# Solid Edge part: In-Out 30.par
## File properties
Title: In - Out 30
Author: DESYS
Template: Normal.par
Last saved by: s.pallini
Revision: 8
Application: Solid Edge
Tipo di contenuto documento: 0
Precisione: 0,990
Document Number: 8020
Revision: 0
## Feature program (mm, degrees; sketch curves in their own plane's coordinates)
sketch for "unnamed RevolvedProtrusion 1" plane through (0, 0, 0) normal (0, -1, 0) x-axis (1, 0, 0)
  line (-147.5, 40.4136) -> (-147.5, 38.4136)
  arc centre (-145.5, 38.4136) radius 2 from (-147.5, 38.4136) to (-145.5, 36.4136) ccw
  line (-145.5, 36.4136) -> (-141.6472, 36.4136)
  arc centre (-141.6472, 31.4136) radius 5 from (-136.6496, 31.2592) to (-141.6472, 36.4136) ccw
  arc centre (-16.7068, 27.5544) radius 120 from (-136.6496, 31.2592) to (-72.9674, -78.4396) ccw
  arc centre (-80, -91.6889) radius 15 from (-65, -91.6889) to (-72.9674, -78.4396) ccw
  line (-65, -108.5864) -> (-65, -91.6889)
  arc centre (-59, -108.5864) radius 6 from (-65, -108.5864) to (-59, -114.5864) ccw
  line (-25, -114.5864) -> (-59, -114.5864)
  line (-25, -74.5864) -> (-25, -114.5864)
  arc centre (-17.1637, 35.1341) radius 110 from (-127.0888, 39.1923) to (-25, -74.5864) ccw
  arc centre (-133.0847, 39.4136) radius 6 from (-127.0888, 39.1923) to (-133.0847, 45.4136) ccw
  line (-142.5, 45.4136) -> (-133.0847, 45.4136)
  arc centre (-142.5, 40.4136) radius 5 from (-147.5, 40.4136) to (-142.5, 45.4136) cw
  dimension (linear) = 25
revolve "unnamed RevolvedProtrusion 1" add full turn 360 deg
fillet "unnamed Round 1"
fillet "Rotondo_2" radius 3
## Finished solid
Body 1: solid body, 16 faces, 16 edges, 0 vertices.
  Faces by surface: torus 10, cylinder 3, plane 3
  Edges by curve: circle 16
Bounding box of the edges (mm; curved faces can reach further): 295.000 x 295.000 x 160.000, from (-147.5, -147.5, -114.5864) to (147.5, 147.5, 45.4136).
Cylindrical faces by radius (mm): R25 x1, R65 x1, R147.5 x1
Toroidal faces (ring radius, tube radius in mm): R16.7068 r120 x1, R17.1637 r110 x1, R28 r3 x1, R35 r10 x1, R59 r6 x1, R80 r15 x1, R133.0847 r6 x1, R141.6472 r5 x1, R142.5 r5 x1, R145.5 r2 x1
Planar faces by outward normal: +z 1, -z 2
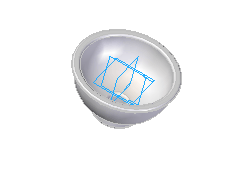
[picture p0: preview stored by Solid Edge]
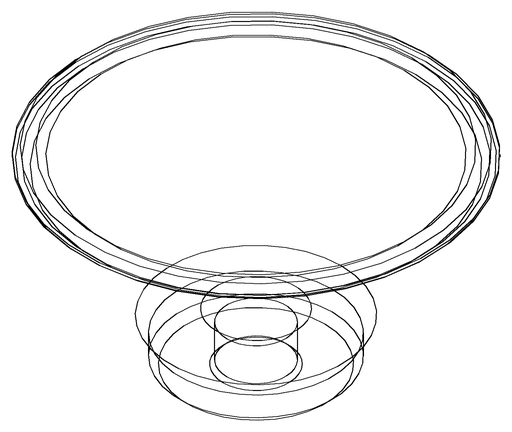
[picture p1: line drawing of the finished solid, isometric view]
